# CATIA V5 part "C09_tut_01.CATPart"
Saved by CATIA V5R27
Part number: Part1
Bounding box of the stored display mesh (mm): x -75 to 140, y -40 to 40, z 0 to 100
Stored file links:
  E:\_Deepak\2017_Deepak\CATIA\Resources\Tutorial Files\Tutorials\c09_catia_v5_6r2016_tut\C09_tut_01.CATPart
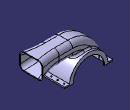
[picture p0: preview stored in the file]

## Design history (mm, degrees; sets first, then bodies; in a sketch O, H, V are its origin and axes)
Body1 (main body)
  Sketch1 on zx-plane, origin (0, 0, 0), H (-1, 0, 0), V (0, 0, 1)
    arc A1 centre (0, 0) radius 60 from (60, 0) to (-60, 0) ccw
    line L1 (-60, 0) -> (60, 0)
    point P1 (-60, 0)
    radius A1 = 60
    coincidence: P1 H
    horizontal: L1 H
  Pad1: profile Sketch1, direction (0, 1, 0), length 40, mirrored extent
  Sketch2 on zx-plane, origin (0, 0, 0), H (-1, 0, 0), V (0, 0, 1)
    point P1 (-82, 100)
    line L1 (-82, 100) -> (-40, 100)
    arc A1 centre (-40, 0) radius 100 from (-40, 100) to (60, 0) cw
    point P4 (60, 0)
    reference projected line E1 (-60, 0) -> (60, 0) from edge [face of Pad1 from Sketch1.L1 | end face of Pad1]
    reference projected point E2 (60, 0) from edge [face of Pad1 from Sketch1.A1 | face of Pad1 from Sketch1.L1]
    reference projected arc E3 centre (0, 0) radius 60 from (60, 0) to (-60, 0) ccw from edge [face of Pad1 from Sketch1.A1 | end face of Pad1]
    distance P1 E1 = 100
    distance P1 V = 82
    horizontal: L1 H
    tangency: A1 L1, A1 E3
    coincidence: P4 E2
  Plane1: type Normal, Curve Sketch2, RefPoint Sketch2.P1, Ratio 0
  Sketch3 on Plane1, origin (82, 0, 0), H (0, 1, 0), V (0, 0, 1)
    line L1 (-29, 100) -> (29, 100)
    line L2 (29, 100) -> (29, 58)
    line L3 (29, 58) -> (-29, 58)
    line L4 (-29, 58) -> (-29, 100)
    reference projected point E1 (0, 100) from Sketch2.P1
    distance L4 V = 29
    length L1 = 58
    length L2 = 42
    horizontal: L1 H, L3 H
    vertical: L2 V, L4 V
    coincidence: L1 E1
  Rib1: profile Sketch3, centre curve Sketch2
  Plane2: type Offset, RefPlane face of Rib1, Offset 58, reversed
  Sketch4 on Plane2, origin (140, 0, 0), H (0, -1, 0), V (0, 0, 1)
    line L1 (36.53, 100) -> (-36.47, 100)
    line L2 (-36.47, 100) -> (-36.47, 47)
    line L3 (-36.47, 47) -> (36.53, 47)
    line L4 (36.53, 47) -> (36.53, 100)
    reference projected line E1 (40, 0) -> (-40, 0) from edge [face of Rib1 | face of Pad1 from Sketch1.A1]
    distance L4 V = 36.53
    distance L1 E1 = 100
    length L2 = 53
    length L1 = 73
    horizontal: L1 H, L3 H
    vertical: L2 V, L4 V
  Loft1: solid, Sections ({boundary Boundary {extract ExtractElem face of Rib1}}; Sketch4), StartFace face of Rib1
  Fillet1: radius 15, on edge [face of Rib1 | face of Rib1] (x3); edge [face of Loft1 | face of Loft1]
  Shell1: ExtOffset 0, Face (face of Rib1; face of Loft1), IntOffset 2.5
  Fillet2: radius 5, on edge [face of Pad1 from Sketch1.A1 | face of Fillet1]
  Sketch5 on end face of Pad1, origin (0, 40, 0), H (-1, 0, 0), V (0, 0, 1)
    arc A1 centre (0, 0) radius 49 from (49, 0) to (-49, 0) ccw
    line L1 (-49, 0) -> (49, 0)
    point P1 (-49, 0)
    radius A1 = 49
    coincidence: P1 H
    horizontal: L1 H
  Pocket1: profile Sketch5, direction (0, -1, 0), through (limit type 6)
  Sketch6 on start face of Pad1, origin (0, -40, 0), H (1, 0, 0), V (0, 0, 1)
    circle A1 centre (0, 0) radius 15
    radius A1 = 15
  Pocket2: profile Sketch6, direction (0, 1, 0), through (limit type 6)
  Sketch7 on end face of Pad1, origin (0, 40, 0), H (-1, 0, 0), V (0, 0, 1)
    line L1 (60, 0) -> (75, 0)
    line L2 (75, 0) -> (75, 4)
    line L3 (75, 4) -> (59.8665, 4)
    point P4 (59.8665, 4)
    reference projected line E1 (-60, 0) -> (60, 0) from edge [face of Rib1 | end face of Pad1]
    reference intersected line E2 (60, 0) -> (-60, 0) from face of Rib1
    reference projected arc E3 centre (0, 0) radius 60 from (60, 0) to (-60, 0) ccw from edge [face of Pad1 from Sketch1.A1 | end face of Pad1]
    point P5 (60, 0)
    construction arc A1 centre (0, 0) radius 60 from (60, 0) to (-59.9992, -0.3191) ccw
    arc A2 centre (0, 0) radius 60 from (60, 0) to (59.8665, 4) ccw
    reference projected line E4 (-60, 0) -> (60, 0) from edge [face of Rib1 | end face of Pad1]
    reference projected arc E5 centre (0, 0) radius 60 from (60, 0) to (-60, 0) ccw from edge [face of Pad1 from Sketch1.A1 | end face of Pad1]
    reference projected arc E6 centre (0, 0) radius 60 from (60, 0) to (-60, 0) ccw from edge [face of Pad1 from Sketch1.A1 | end face of Pad1]
    reference projected arc E7 centre (0, 0) radius 60 from (60, 0) to (-60, 0) ccw from edge [face of Pad1 from Sketch1.A1 | end face of Pad1]
    length L2 = 4
    distance L2 V = 75
    horizontal: L1 H, L3 H
    vertical: L2 V
    coincidence: L1 E1, L1 E2, P4 E3, A2 A1, P5 E4, A2 E5
    concentricity: A2 A1, A2 E6
    tangency: A2 A1, A2 E7
  Pad2: profile Sketch7, direction (0, -1, 0), length 80
  Mirror1: of Pad2, about yz-plane
  Sketch8 on face of Mirror1, origin (0, 0, 4), H (1, 0, 0), V (0, 1, 0)
    point P1 (-67, 30)
    reference projected line E1 (-75, 40) -> (-59.8665, 40) from edge [face of Pad2 from Sketch7.L3 | face of Mirror1]
    reference projected line E2 (-75, 40) -> (-75, -40) from edge [face of Pad2 from Sketch7.L2 | face of Pad2 from Sketch7.L3]
    point P2 (67, 30)
    distance E1 P1 = 10
    distance P1 E2 = 8
    symmetry: P1 P2 V
  Sketch9 on face of Pad2 from Sketch7.L3, origin (-67, 30, 4), H (1, 0, 0), V (0, 1, 0)
    point P1 (0, 0)
    reference projected point E1 (0, 0) from Sketch8.P1
    coincidence: E1 P1
  Hole1: placed by Sketch9, at (-67, 30, 4) direction (0, 0, -1), diameter 4, through (limit type 6)
  RectPattern1: of Hole1, direction 1 instances 4, spacing 20, along edge [face of Pad2 from Sketch7.L2 | face of Pad2 from Sketch7.L3]
  Sketch10 on face of Mirror1, origin (67, 30, 4), H (1, 0, 0), V (0, 1, 0)
    point P1 (0, 0)
    reference projected point E1 (0, 0) from Sketch8.P2
    coincidence: E1 P1
  Hole2: placed by Sketch10, at (67, 30, 4) direction (0, 0, -1), diameter 4, through (limit type 6)
  RectPattern2: of Hole2, direction 1 instances 4, spacing 20, along edge [face of Mirror1 | face of Mirror1]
